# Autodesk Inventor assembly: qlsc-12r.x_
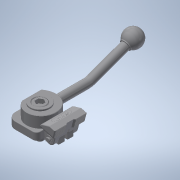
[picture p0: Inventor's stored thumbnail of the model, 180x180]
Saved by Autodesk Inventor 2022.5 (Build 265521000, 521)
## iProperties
Part Number: qlsc-12r.x_
Material: 一般
Document SubType Name: Assembly
Designer: ImaoCorp
Sending System: SOLIDWORKS 2017-2017317
MC: AMD64
MC_MODEL: Intel64 Family 6 Model 60 Stepping 3, GenuineIntel
OS: Windows_NT
FRU: Parasolid Version 29.0, build 201,  4-17-2017
FORMAT: text
GUISE: transmit
KEY: qlsc-12r
FILE: qlsc-12r.x_t
DATE: Wed Sep 04 15:42:18 2019
Author: ImaoCorp
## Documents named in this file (4)
- X:\14_SW2022-Inv2022\00_全2023-1023新製品(TCC)まで\q\qlsc-12r\QLSC-12R.iam
- X:\14_SW2022-Inv2022\00_全2023-1023新製品(TCC)まで\q\qlsc-12r\qlsc-12r_01.ipt
- X:\14_SW2022-Inv2022\00_全2023-1023新製品(TCC)まで\q\qlsc-12r\qlsc-12r_02.ipt
- X:\14_SW2022-Inv2022\00_全2023-1023新製品(TCC)まで\q\qlsc-12r\qlsc-12r_03.ipt
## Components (3 placed, 3 different names)
1. qlsc-12r_01
2. qlsc-12r_02
3. qlsc-12r_03
